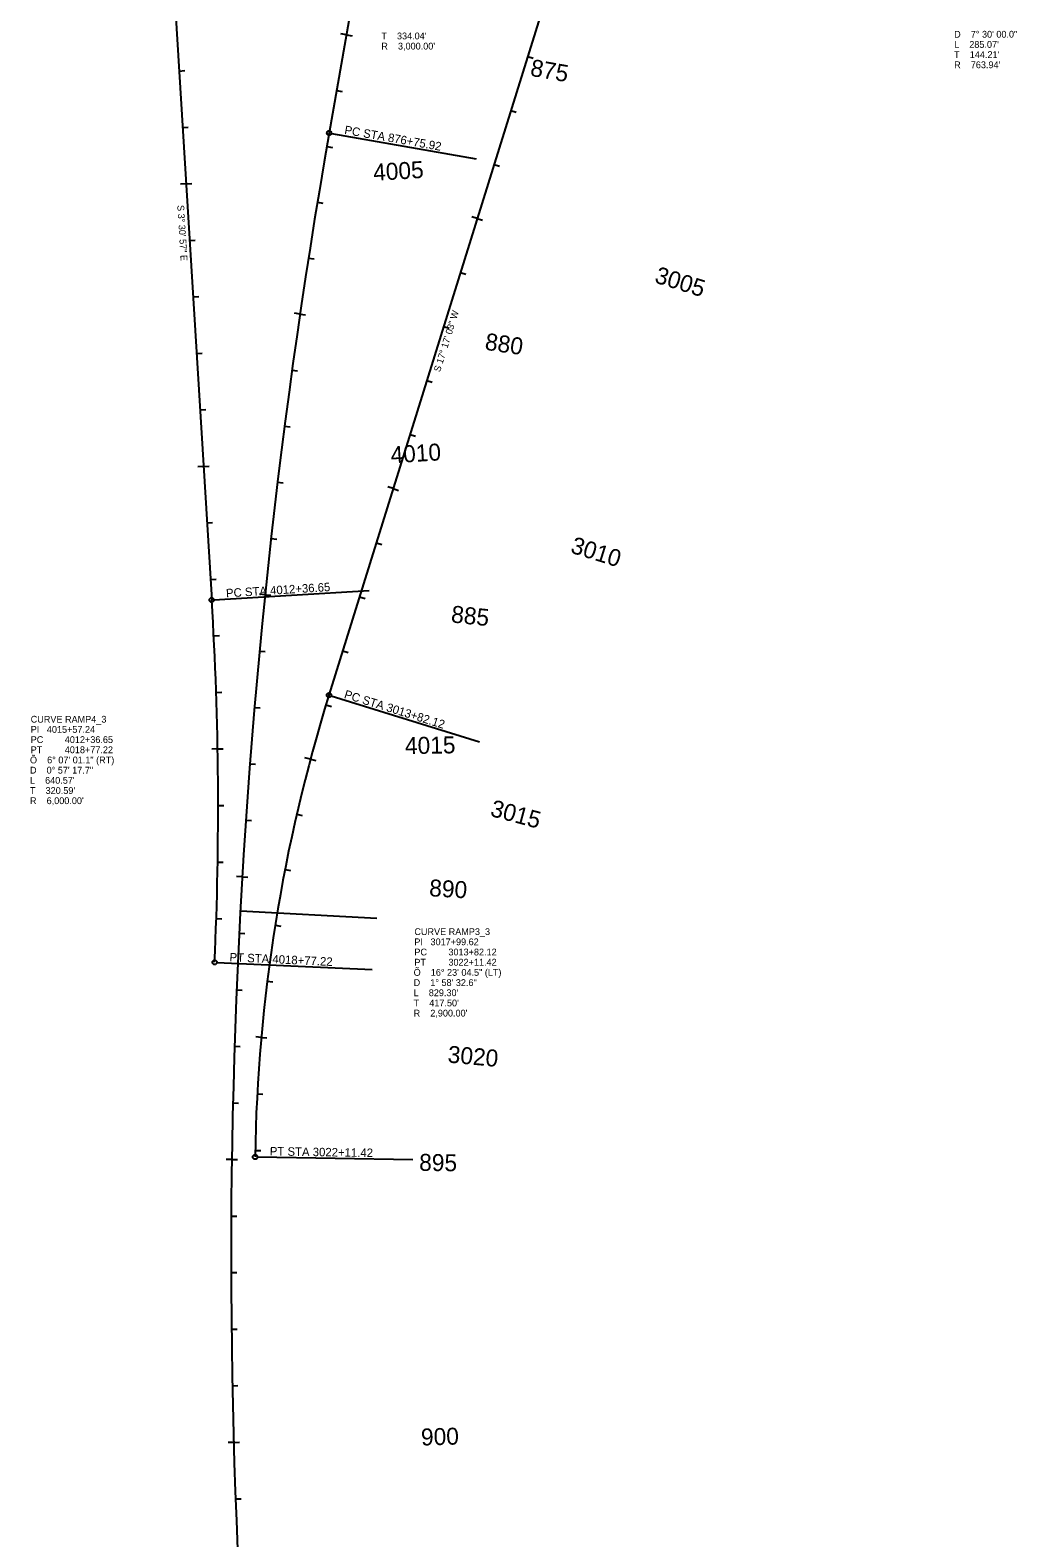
# Model space of a CAD drawing. Extents: x 2819977 to 2827606, y 116785 to 150320.
# Drawn here: x 2820479 to 2822222, y 129327 to 131991 of the extents above; entities that cross this region are included whole.
import ezdxf

# ---------------------------------------------------------------- set-up
doc = ezdxf.new("R2010")
doc.units = 0
for name, color, linetype in [('Default', 7, 'Continuous'), ('Modeling-Contours-Minor-Existing', 7, 'Continuous'), ('Modeling-Flow Arrows-Existing', 7, 'Continuous'), ('Modeling-Spot-Existing', 7, 'Continuous'), ('Modeling-Triangle Verticies-Existing', 7, 'Continuous'), ('Modeling-Triangles-Existing', 7, 'Continuous')]:
    doc.layers.add(name, color=color, linetype=linetype)

msp = doc.modelspace()

# ---------------------------------------------------------------- linework, layer by layer
at = {"layer": 'Default'}
msp.add_line((2821447.5, 134317.2), (2821007.1, 131809.7), dxfattribs=at)
for centre, radius, start, end in [((2832333.7, 129820.2), 11500, 170.03806, 202.7163), ((2814810.8, 130616.3), 6000, 357.39887, 3.51583), ((2823775.7, 129954.6), 2900, 162.7159, 179.1005)]:
    msp.add_arc(centre, radius, start, end, dxfattribs=at)
at = {"layer": 'Modeling-Flow Arrows-Existing'}
for p, q in [((2821447.5, 134317.2), (2821007.1, 131809.7)), ((2820723.6, 132218.6), (2820799.5, 130984.2)), ((2821417.3, 132135.9), (2821006.7, 130816.2)), ((2821037.5, 131982.9), (2821027.7, 131984.7)), ((2821037.5, 131982.9), (2821047.4, 131981.2)), ((2821357.9, 131945), (2821367.5, 131942)), ((2820742, 131919.1), (2820752, 131919.8)), ((2821020.2, 131884.5), (2821030.1, 131882.7)), ((2821328.2, 131849.5), (2821337.8, 131846.5)), ((2820748.2, 131819.3), (2820758.1, 131819.9)), ((2821002.9, 131786), (2821012.8, 131784.2)), ((2821298.5, 131754), (2821308, 131751)), ((2820754.3, 131719.5), (2820744.3, 131718.9)), ((2820754.3, 131719.5), (2820764.3, 131720.1)), ((2820986.3, 131687.4), (2820996.1, 131685.7)), ((2821268.8, 131658.5), (2821259.2, 131661.5)), ((2821268.8, 131658.5), (2821278.3, 131655.5)), ((2820760.4, 131619.7), (2820770.4, 131620.3)), ((2820970.5, 131588.6), (2820980.3, 131587.1)), ((2821239.1, 131563), (2821248.6, 131560.1)), ((2820766.6, 131519.9), (2820776.5, 131520.5)), ((2820955.5, 131489.7), (2820945.6, 131491.2)), ((2820955.5, 131489.7), (2820965.4, 131488.3)), ((2821209.4, 131467.6), (2821218.9, 131464.6)), ((2820772.7, 131420.1), (2820782.7, 131420.7)), ((2820941.4, 131390.7), (2820951.3, 131389.4)), ((2821179.7, 131372.1), (2821189.2, 131369.1)), ((2820778.8, 131320.3), (2820788.8, 131320.9)), ((2820928.2, 131291.6), (2820938.1, 131290.3)), ((2821149.9, 131276.6), (2821159.5, 131273.6)), ((2820785, 131220.5), (2820794.9, 131221.1)), ((2820785, 131220.5), (2820775, 131219.8)), ((2820915.8, 131192.4), (2820925.8, 131191.2)), ((2821120.2, 131181.1), (2821110.7, 131184.1)), ((2821120.2, 131181.1), (2821129.8, 131178.1)), ((2820791.1, 131120.6), (2820801.1, 131121.3)), ((2820904.3, 131093), (2820914.3, 131091.9)), ((2821090.5, 131085.6), (2821100.1, 131082.6)), ((2820797.2, 131020.8), (2820807.2, 131021.4)), ((2820893.7, 130993.6), (2820883.8, 130994.6)), ((2820893.7, 130993.6), (2820903.7, 130992.6)), ((2821060.8, 130990.1), (2821070.4, 130987.2)), ((2820803, 130921), (2820813, 130921.5)), ((2820883.9, 130894.1), (2820893.9, 130893.2)), ((2821031.1, 130894.6), (2821040.7, 130891.7)), ((2820807.3, 130821.1), (2820817.3, 130821.4)), ((2820875, 130794.5), (2820885, 130793.6)), ((2821001.4, 130799.1), (2821011, 130796.2)), ((2820809.8, 130721.1), (2820799.9, 130721)), ((2820809.8, 130721.1), (2820819.8, 130721.3)), ((2820867, 130694.8), (2820877, 130694)), ((2820974, 130703), (2820964.3, 130705.6)), ((2820974, 130703), (2820983.6, 130700.4)), ((2820810.8, 130621.1), (2820820.8, 130621.1)), ((2820859.8, 130595.1), (2820869.8, 130594.4)), ((2820949.8, 130606), (2820959.6, 130603.7)), ((2820810, 130521.1), (2820820, 130521)), ((2820929.1, 130508.1), (2820938.9, 130506.2)), ((2820853.5, 130495.3), (2820843.5, 130495.9)), ((2820853.5, 130495.3), (2820863.5, 130494.7)), ((2820807.6, 130421.2), (2820817.6, 130420.8)), ((2820848.1, 130395.4), (2820858.1, 130394.9)), ((2820911.7, 130409.7), (2820921.5, 130408.1)), ((2820843.5, 130295.5), (2820853.5, 130295.1)), ((2820897.7, 130310.7), (2820907.6, 130309.4)), ((2820887.1, 130211.2), (2820877.2, 130212.1)), ((2820887.1, 130211.2), (2820897.1, 130210.3)), ((2820839.8, 130195.6), (2820849.8, 130195.3)), ((2820880, 130111.5), (2820890, 130110.9)), ((2820837, 130095.6), (2820847, 130095.4)), ((2820835, 129995.6), (2820825, 129995.8)), ((2820835, 129995.6), (2820845, 129995.5)), ((2820876.3, 130011.6), (2820886.3, 130011.4)), ((2820833.9, 129895.7), (2820843.9, 129895.6)), ((2820833.7, 129795.7), (2820843.7, 129795.7)), ((2820834.4, 129695.7), (2820844.4, 129695.8)), ((2820835.9, 129595.7), (2820845.9, 129595.9)), ((2820838.3, 129495.7), (2820828.3, 129495.4)), ((2820838.3, 129495.7), (2820848.3, 129496)), ((2820841.5, 129395.8), (2820851.5, 129396.1))]:
    msp.add_line(p, q, dxfattribs=at)
for centre, radius, start, end in [((2832333.7, 129820.2), 11500, 170.03806, 202.7163), ((2814810.8, 130616.3), 6000, 357.39887, 3.51583), ((2823775.7, 129954.6), 2900, 162.7159, 179.1005)]:
    msp.add_arc(centre, radius, start, end, dxfattribs=at)
at = {"layer": 'Modeling-Spot-Existing'}
for p, q in [((2821011, 131809), (2821266.9, 131764)), ((2820803.5, 130984.5), (2821077.7, 131001.3)), ((2821010.5, 130815), (2821272.9, 130733.4)), ((2820808.6, 130343.8), (2821083, 130331.4)), ((2820880.1, 130000.1), (2821154.8, 129995.8))]:
    msp.add_line(p, q, dxfattribs=at)
for centre in [(2821007.1, 131809.7), (2820799.5, 130984.2), (2821006.7, 130816.2), (2820804.6, 130344), (2820876.1, 130000.1)]:
    msp.add_circle(centre, 4, dxfattribs=at)
at = {"layer": 'Modeling-Triangles-Existing'}
msp.add_line((2820850.1, 130435.1), (2821091.4, 130422.2), dxfattribs=at)

# ---------------------------------------------------------------- texts
at = {"layer": 'Modeling-Contours-Minor-Existing'}
for s, rotation, p in [('S 3%%d 30\' 57" E', 273.5158, (2820738.6, 131681.9)), ('S 17%%d 17\' 03" W', 72.7159, (2821203, 131386.4))]:
    msp.add_text(s, height=12, rotation=rotation, dxfattribs=at).set_placement(p)
at = {"layer": 'Modeling-Flow Arrows-Existing'}
for s, rotation, p in [(' 875', 350.0381, (2821350.1, 131912.8)), (' 4005', 3.5158, (2821074.6, 131724.2)), (' 3005', 342.7159, (2821569.9, 131549.1)), (' 880', 351.6527, (2821270, 131428.4)), (' 4010', 3.5158, (2821105.3, 131225.1)), (' 3010', 342.7159, (2821421.3, 131071.7)), (' 885', 354.1438, (2821210.5, 130946)), (' 4015', 1.0011, (2821130.1, 130711.7)), (' 3015', 345.0448, (2821279.3, 130605.9)), (' 890', 356.635, (2821172.1, 130461.5)), (' 3020', 354.9234, (2821204.5, 130168)), (' 895', 359.1261, (2821154.8, 129975.8)), (' 900', 1.6172, (2821158.6, 129489.7))]:
    msp.add_text(s, height=30, rotation=rotation, dxfattribs=at).set_placement(p)
at = {"layer": 'Modeling-Spot-Existing'}
for s, rotation, p in [('PC STA 876+75.92', 350.0381, (2821033.2, 131808.1)), ('PC STA 4012+36.65', 3.5158, (2820825.2, 130988.8)), ('PC STA 3013+82.12', 342.7159, (2821032.4, 130811.4)), ('PT STA 4018+77.22', 357.3989, (2820830.7, 130345.8)), ('PT STA 3022+11.42', 359.1005, (2820902.1, 130002.7))]:
    msp.add_text(s, height=15, rotation=rotation, dxfattribs=at).set_placement(p)
at = {"layer": 'Modeling-Triangle Verticies-Existing'}
for s, p in [("T    334.04'", (2821099.2, 131975.1)), ("R    3,000.00'", (2821099.2, 131957.1)), ('D    7%%d 30\' 00.0"', (2822111.5, 131978.1)), ("L    285.07'", (2822111.5, 131960.1)), ("T    144.21'", (2822111.5, 131942.1)), ("R    763.94'", (2822111.5, 131924.1)), ('CURVE RAMP4_3', (2820479.6, 130767.6)), ('PI   4015+57.24', (2820479.6, 130749.6)), ('PC', (2820479.6, 130731.6)), ('4012+36.65', (2820539.8, 130731.6)), ('PT', (2820479.6, 130713.6)), ('4018+77.22', (2820539.8, 130713.6)), ('Õ    6%%d 07\' 01.1" (RT)', (2820478.3, 130695.6)), ('D    0%%d 57\' 17.7"', (2820478.3, 130677.6)), ("L    640.57'", (2820478.3, 130659.6)), ("T    320.59'", (2820478.3, 130641.6)), ("R    6,000.00'", (2820478.3, 130623.6)), ('CURVE RAMP3_3', (2821157.6, 130392.2)), ('PI   3017+99.62', (2821157.6, 130374.2)), ('PC', (2821157.6, 130356.2)), ('3013+82.12', (2821217.8, 130356.2)), ('PT', (2821157.6, 130338.2)), ('3022+11.42', (2821217.8, 130338.2)), ('Õ    16%%d 23\' 04.5" (LT)', (2821156.3, 130320.2)), ('D    1%%d 58\' 32.6"', (2821156.3, 130302.2)), ("L    829.30'", (2821156.3, 130284.2)), ("T    417.50'", (2821156.3, 130266.2)), ("R    2,900.00'", (2821156.3, 130248.2))]:
    msp.add_text(s, height=12, dxfattribs=at).set_placement(p)

doc.saveas('drawing.dxf')
